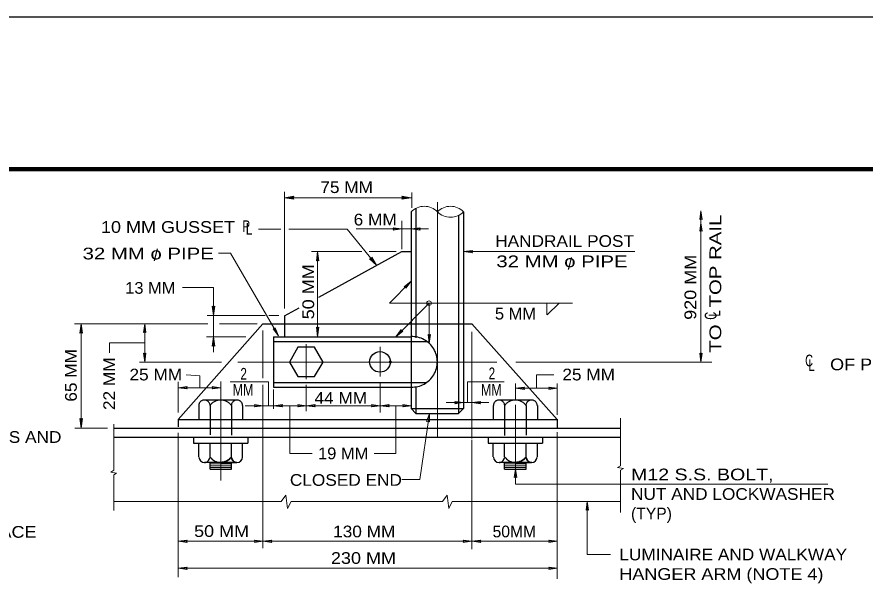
# Model space of a CAD drawing. Extents: x 312601.858 to 312602.699, y 144420.109 to 144420.704.
# Drawn here: x 312602.2633 to 312602.4805, y 144420.5557 to 144420.7035 of the extents above; entities that cross this region are included whole.
import ezdxf
from ezdxf.enums import TextEntityAlignment as Align

# ---------------------------------------------------------------- set-up
doc = ezdxf.new("R2010")
doc.units = 0
doc.header["$LTSCALE"] = 0.0012
doc.header["$PDMODE"] = 32
doc.header["$PDSIZE"] = 0.0006
for name, pattern in [('DOT_DASHED', [7.7, 5, -1.2, 0.3, -1.2]), ('LONG_DASHED', [7.5, 6, -1.5]), ('MEDIUM_DASHED', [4.5, 3, -1.5])]:
    doc.linetypes.add(name, pattern=pattern)
for name, color, linetype, lineweight in [('1', 7, 'Continuous', 13), ('2', 7, 'Continuous', 13), ('39', 7, 'Continuous', 13), ('4', 7, 'Continuous', 13)]:
    doc.layers.add(name, color=color, linetype=linetype, lineweight=lineweight)

msp = doc.modelspace()

# ---------------------------------------------------------------- hatches: boundary and pattern name
at = {"layer": '39'}
for points in [[(312602.334, 144420.6572), (312602.3342, 144420.6568), (312602.3318, 144420.6572), (312602.3342, 144420.6576)], [(312602.334, 144420.6572), (312602.3342, 144420.6568), (312602.3318, 144420.6572), (312602.3342, 144420.6576)], [(312602.3621, 144420.6572), (312602.3619, 144420.6576), (312602.3643, 144420.6572), (312602.3619, 144420.6568)], [(312602.3403, 144420.6412), (312602.34, 144420.641), (312602.3403, 144420.6434), (312602.3406, 144420.641)], [(312602.3403, 144420.6412), (312602.34, 144420.641), (312602.3403, 144420.6434), (312602.3406, 144420.641)], [(312602.354, 144420.6416), (312602.3542, 144420.642), (312602.3554, 144420.6399), (312602.3536, 144420.6415)], [(312602.3136, 144420.6292), (312602.314, 144420.6294), (312602.3136, 144420.627), (312602.3133, 144420.6294)], [(312602.2797, 144420.6227), (312602.2794, 144420.6225), (312602.2797, 144420.6249), (312602.2801, 144420.6225)], [(312602.3403, 144420.6238), (312602.3406, 144420.624), (312602.3403, 144420.6216), (312602.34, 144420.624)], [(312602.3136, 144420.6194), (312602.3133, 144420.6192), (312602.3136, 144420.6216), (312602.314, 144420.6192)], [(312602.3757, 144420.6047), (312602.3755, 144420.605), (312602.3777, 144420.6047), (312602.3755, 144420.6044)], [(312602.3818, 144420.6047), (312602.382, 144420.6044), (312602.3798, 144420.6047), (312602.382, 144420.605)], [(312602.2797, 144420.6004), (312602.2801, 144420.6006), (312602.2797, 144420.5982), (312602.2794, 144420.6006)]]:
    msp.add_hatch(color=256, dxfattribs=at).paths.add_polyline_path(points)

# ---------------------------------------------------------------- linework, layer by layer
at = {"layer": '1'}
for p, q in [((312602.3318, 144420.6587), (312602.3318, 144420.6288)), ((312602.3644, 144420.6546), (312602.3644, 144420.6585)), ((312602.3318, 144420.6572), (312602.3643, 144420.6572)), ((312602.3619, 144420.644), (312602.3619, 144420.6513)), ((312602.3252, 144420.6491), (312602.3309, 144420.6491)), ((312602.3329, 144420.6491), (312602.3479, 144420.6491)), ((312602.3479, 144420.6491), (312602.3554, 144420.6399)), ((312602.4385, 144420.6508), (312602.4385, 144420.6151)), ((312602.3149, 144420.643), (312602.318, 144420.643)), ((312602.318, 144420.643), (312602.3303, 144420.6218)), ((312602.3387, 144420.6434), (312602.3516, 144420.6434)), ((312602.3403, 144420.6434), (312602.3403, 144420.6216)), ((312602.3535, 144420.6434), (312602.3604, 144420.6434)), ((312602.3777, 144420.6434), (312602.4216, 144420.6434)), ((312602.3587, 144420.6302), (312602.3643, 144420.6358)), ((312602.3587, 144420.6302), (312602.4056, 144420.6302)), ((312602.3689, 144420.6302), (312602.3603, 144420.6216)), ((312602.3689, 144420.6301), (312602.3689, 144420.6199)), ((312602.399, 144420.6302), (312602.399, 144420.6272)), ((312602.3991, 144420.6272), (312602.4022, 144420.6302)), ((312602.3269, 144420.627), (312602.312, 144420.627)), ((312602.3304, 144420.627), (312602.3278, 144420.627)), ((312602.278, 144420.6249), (312602.3122, 144420.6249)), ((312602.2797, 144420.6249), (312602.2797, 144420.5982)), ((312602.296, 144420.6249), (312602.296, 144420.6152)), ((312602.3152, 144420.6249), (312602.3248, 144420.6249)), ((312602.3263, 144420.6232), (312602.3263, 144420.611)), ((312602.3118, 144420.6216), (312602.3219, 144420.6216)), ((312602.3136, 144420.6216), (312602.3136, 144420.6176)), ((312602.3798, 144420.6228), (312602.3798, 144420.5955)), ((312602.287, 144420.62), (312602.287, 144420.6175)), ((312602.2947, 144420.6151), (312602.3157, 144420.6151)), ((312602.3911, 144420.6151), (312602.4413, 144420.6151)), ((312602.3046, 144420.61), (312602.3046, 144420.6022)), ((312602.3179, 144420.61), (312602.3277, 144420.61)), ((312602.3787, 144420.61), (312602.3881, 144420.61)), ((312602.3046, 144420.6085), (312602.3155, 144420.6085)), ((312602.3263, 144420.6093), (312602.3263, 144420.5952)), ((312602.329, 144420.6081), (312602.329, 144420.6031)), ((312602.3563, 144420.6097), (312602.3563, 144420.6022)), ((312602.391, 144420.6096), (312602.391, 144420.6055)), ((312602.391, 144420.6084), (312602.4017, 144420.6084)), ((312602.4017, 144420.6096), (312602.4017, 144420.6016)), ((312602.3563, 144420.6039), (312602.3643, 144420.6039)), ((312602.2881, 144420.5992), (312602.2881, 144420.5874)), ((312602.4179, 144420.6007), (312602.4179, 144420.5885)), ((312602.2781, 144420.5982), (312602.2865, 144420.5982)), ((312602.3046, 144420.597), (312602.3046, 144420.56)), ((312602.4017, 144420.5971), (312602.4017, 144420.5596)), ((312602.3263, 144420.5952), (312602.3263, 144420.5674)), ((312602.3798, 144420.5952), (312602.3798, 144420.5672)), ((312602.3128, 144420.589), (312602.3182, 144420.589)), ((312602.3128, 144420.5885), (312602.3182, 144420.5885)), ((312602.3128, 144420.5881), (312602.3182, 144420.5881)), ((312602.3155, 144420.5894), (312602.3196, 144420.5894)), ((312602.3882, 144420.589), (312602.3937, 144420.589)), ((312602.3882, 144420.5885), (312602.3937, 144420.5885)), ((312602.3882, 144420.5881), (312602.3937, 144420.5881)), ((312602.4171, 144420.5881), (312602.4179, 144420.5885)), ((312602.4171, 144420.5881), (312602.4187, 144420.5878)), ((312602.2873, 144420.5869), (312602.2881, 144420.5874)), ((312602.2873, 144420.5869), (312602.2888, 144420.5866)), ((312602.2881, 144420.5862), (312602.2888, 144420.5866)), ((312602.2881, 144420.5862), (312602.2881, 144420.5771)), ((312602.391, 144420.5877), (312602.391, 144420.5838)), ((312602.4179, 144420.5874), (312602.4187, 144420.5878)), ((312602.4179, 144420.5874), (312602.4179, 144420.5766)), ((312602.391, 144420.5838), (312602.471, 144420.5838)), ((312602.2881, 144420.5794), (312602.331, 144420.5794)), ((312602.3335, 144420.5794), (312602.3723, 144420.5794)), ((312602.3748, 144420.5794), (312602.4179, 144420.5794)), ((312602.4094, 144420.5794), (312602.4094, 144420.5658)), ((312602.4094, 144420.5658), (312602.4153, 144420.5658)), ((312602.3046, 144420.5623), (312602.4017, 144420.5623))]:
    msp.add_line(p, q, dxfattribs=at)
at = {"layer": '1', "linetype": 'DOT_DASHED'}
for p, q in [((312602.371, 144420.6561), (312602.371, 144420.5959)), ((312602.3563, 144420.619), (312602.3563, 144420.6114)), ((312602.3199, 144420.6151), (312602.3862, 144420.6151)), ((312602.3155, 144420.6101), (312602.3155, 144420.5848)), ((312602.391, 144420.6041), (312602.391, 144420.5877))]:
    msp.add_line(p, q, dxfattribs=at)
at = {"layer": '1', "lineweight": 25}
for p, q in [((312602.3643, 144420.6536), (312602.3643, 144420.6249)), ((312602.3777, 144420.6536), (312602.3777, 144420.6249)), ((312602.3406, 144420.6317), (312602.3619, 144420.6434)), ((312602.3619, 144420.6434), (312602.3643, 144420.6434)), ((312602.3318, 144420.6269), (312602.3356, 144420.629)), ((312602.3318, 144420.6269), (312602.3318, 144420.6249)), ((312602.3046, 144420.6004), (312602.3263, 144420.6249)), ((312602.3263, 144420.6249), (312602.3798, 144420.6249)), ((312602.3798, 144420.6249), (312602.4017, 144420.6004)), ((312602.3046, 144420.6004), (312602.3046, 144420.5985)), ((312602.4017, 144420.6005), (312602.4017, 144420.5982)), ((312602.2881, 144420.5982), (312602.4179, 144420.5982)), ((312602.2881, 144420.5959), (312602.4179, 144420.5959)), ((312602.3224, 144420.5959), (312602.3224, 144420.5943)), ((312602.3979, 144420.5959), (312602.3979, 144420.5943)), ((312602.3099, 144420.5908), (312602.3099, 144420.5943)), ((312602.3128, 144420.5908), (312602.3128, 144420.5943)), ((312602.3182, 144420.5908), (312602.3182, 144420.5943)), ((312602.3211, 144420.5908), (312602.3211, 144420.5943)), ((312602.3853, 144420.5908), (312602.3853, 144420.5943)), ((312602.3882, 144420.5908), (312602.3882, 144420.5943)), ((312602.3937, 144420.5908), (312602.3937, 144420.5943)), ((312602.3966, 144420.5908), (312602.3966, 144420.5943)), ((312602.3128, 144420.5877), (312602.3128, 144420.5894)), ((312602.3182, 144420.5877), (312602.3182, 144420.5894)), ((312602.3882, 144420.5877), (312602.3882, 144420.5894)), ((312602.391, 144420.5894), (312602.3951, 144420.5894)), ((312602.3937, 144420.5877), (312602.3937, 144420.5894)), ((312602.3128, 144420.5877), (312602.3182, 144420.5877)), ((312602.3882, 144420.5877), (312602.3937, 144420.5877))]:
    msp.add_line(p, q, dxfattribs=at)
at = {"layer": '1', "linetype": 'LONG_DASHED', "lineweight": 25}
for p, q in [((312602.3655, 144420.6545), (312602.3655, 144420.6213)), ((312602.3764, 144420.6527), (312602.3764, 144420.6249)), ((312602.3318, 144420.6249), (312602.3318, 144420.6216)), ((312602.3643, 144420.6249), (312602.3643, 144420.6032)), ((312602.3764, 144420.6249), (312602.3764, 144420.6019)), ((312602.3777, 144420.6249), (312602.3777, 144420.6032)), ((312602.329, 144420.6216), (312602.329, 144420.6087)), ((312602.329, 144420.6216), (312602.3642, 144420.6216)), ((312602.329, 144420.6204), (312602.3683, 144420.6204)), ((312602.329, 144420.6099), (312602.3682, 144420.6099)), ((312602.329, 144420.6087), (312602.3643, 144420.6087)), ((312602.3655, 144420.6088), (312602.3655, 144420.6019)), ((312602.3128, 144420.604), (312602.3128, 144420.5965)), ((312602.3182, 144420.604), (312602.3182, 144420.5964)), ((312602.3882, 144420.604), (312602.3882, 144420.5963)), ((312602.3937, 144420.604), (312602.3937, 144420.5964)), ((312602.3643, 144420.6032), (312602.3655, 144420.6019)), ((312602.3643, 144420.6032), (312602.3777, 144420.6032)), ((312602.3655, 144420.6019), (312602.3764, 144420.6019)), ((312602.3764, 144420.6019), (312602.3777, 144420.6032)), ((312602.3046, 144420.6004), (312602.4016, 144420.6004))]:
    msp.add_line(p, q, dxfattribs=at)
at = {"layer": '1', "linetype": 'MEDIUM_DASHED', "lineweight": 25}
for p, q in [((312602.3099, 144420.604), (312602.3099, 144420.6004)), ((312602.3113, 144420.6054), (312602.3196, 144420.6054)), ((312602.3211, 144420.604), (312602.3211, 144420.6004)), ((312602.3853, 144420.604), (312602.3853, 144420.6004)), ((312602.3868, 144420.6054), (312602.3951, 144420.6054)), ((312602.3966, 144420.604), (312602.3966, 144420.6004))]:
    msp.add_line(p, q, dxfattribs=at)
at = {"layer": '1'}
for points in [[(312602.4382, 144420.6516), (312602.4385, 144420.6538), (312602.4388, 144420.6516), (312602.4385, 144420.6518)], [(312602.3597, 144420.6495), (312602.3619, 144420.6492), (312602.3597, 144420.6489), (312602.3599, 144420.6492)], [(312602.3666, 144420.6489), (312602.3643, 144420.6492), (312602.3666, 144420.6495), (312602.3663, 144420.6492)], [(312602.4382, 144420.6486), (312602.4385, 144420.6508), (312602.4388, 144420.6486), (312602.4385, 144420.6488)], [(312602.38, 144420.6431), (312602.3777, 144420.6434), (312602.38, 144420.6437), (312602.3797, 144420.6434)], [(312602.3625, 144420.6344), (312602.3643, 144420.6358), (312602.3629, 144420.634), (312602.3629, 144420.6344)], [(312602.2957, 144420.6227), (312602.296, 144420.6249), (312602.2963, 144420.6227), (312602.296, 144420.6229)], [(312602.3294, 144420.6239), (312602.3303, 144420.6218), (312602.3289, 144420.6236), (312602.3293, 144420.6236)], [(312602.3621, 144420.623), (312602.3603, 144420.6216), (312602.3617, 144420.6234), (312602.3617, 144420.623)], [(312602.3692, 144420.6222), (312602.3689, 144420.6199), (312602.3686, 144420.6222), (312602.3689, 144420.6219)], [(312602.2963, 144420.6174), (312602.296, 144420.6151), (312602.2957, 144420.6174), (312602.296, 144420.6171)], [(312602.4388, 144420.6174), (312602.4385, 144420.6151), (312602.4382, 144420.6174), (312602.4385, 144420.6171)], [(312602.3069, 144420.6082), (312602.3046, 144420.6085), (312602.3069, 144420.6088), (312602.3066, 144420.6085)], [(312602.3133, 144420.6088), (312602.3155, 144420.6085), (312602.3133, 144420.6082), (312602.3135, 144420.6085)], [(312602.3933, 144420.6081), (312602.391, 144420.6084), (312602.3933, 144420.6087), (312602.393, 144420.6084)], [(312602.3995, 144420.6087), (312602.4017, 144420.6084), (312602.3995, 144420.6081), (312602.3997, 144420.6084)], [(312602.3241, 144420.6042), (312602.3263, 144420.6039), (312602.3241, 144420.6036), (312602.3243, 144420.6039)], [(312602.3313, 144420.6036), (312602.329, 144420.6039), (312602.3313, 144420.6042), (312602.331, 144420.6039)], [(312602.3352, 144420.6042), (312602.3374, 144420.6039), (312602.3352, 144420.6036), (312602.3354, 144420.6039)], [(312602.3397, 144420.6036), (312602.3374, 144420.6039), (312602.3397, 144420.6042), (312602.3394, 144420.6039)], [(312602.3541, 144420.6042), (312602.3563, 144420.6039), (312602.3541, 144420.6036), (312602.3543, 144420.6039)], [(312602.3586, 144420.6036), (312602.3563, 144420.6039), (312602.3586, 144420.6042), (312602.3583, 144420.6039)], [(312602.3621, 144420.6042), (312602.3643, 144420.6039), (312602.3621, 144420.6036), (312602.3623, 144420.6039)], [(312602.3682, 144420.5999), (312602.369, 144420.6019), (312602.369, 144420.5998), (312602.3687, 144420.6)], [(312602.3907, 144420.5855), (312602.391, 144420.5877), (312602.3913, 144420.5855), (312602.391, 144420.5857)], [(312602.4091, 144420.5772), (312602.4094, 144420.5794), (312602.4097, 144420.5772), (312602.4094, 144420.5774)], [(312602.3069, 144420.5689), (312602.3046, 144420.5692), (312602.3069, 144420.5695), (312602.3066, 144420.5692)], [(312602.3241, 144420.5695), (312602.3263, 144420.5692), (312602.3241, 144420.5689), (312602.3243, 144420.5692)], [(312602.3286, 144420.5689), (312602.3263, 144420.5692), (312602.3286, 144420.5695), (312602.3283, 144420.5692)], [(312602.3776, 144420.5695), (312602.3798, 144420.5692), (312602.3776, 144420.5689), (312602.3778, 144420.5692)], [(312602.3821, 144420.5689), (312602.3798, 144420.5692), (312602.3821, 144420.5695), (312602.3818, 144420.5692)], [(312602.3995, 144420.5695), (312602.4017, 144420.5692), (312602.3995, 144420.5689), (312602.3997, 144420.5692)], [(312602.3069, 144420.562), (312602.3046, 144420.5623), (312602.3069, 144420.5626), (312602.3066, 144420.5623)], [(312602.3995, 144420.5626), (312602.4017, 144420.5623), (312602.3995, 144420.562), (312602.3997, 144420.5623)]]:
    msp.add_lwpolyline(points, close=True, dxfattribs=at)
for points in [[(312602.3502, 144420.6492), (312602.3619, 144420.6492), (312602.3643, 144420.6492), (312602.3687, 144420.6492)], [(312602.3136, 144420.6342), (312602.3136, 144420.627), (312602.3136, 144420.6216)], [(312602.3589, 144420.6151), (312602.3593, 144420.6151), (312602.3592, 144420.6151)], [(312602.3217, 144420.6039), (312602.3263, 144420.6039), (312602.329, 144420.6039)], [(312602.329, 144420.6039), (312602.3374, 144420.6039), (312602.3563, 144420.6039), (312602.3563, 144420.6039)], [(312602.3732, 144420.6047), (312602.3777, 144420.6047), (312602.3798, 144420.6047), (312602.3842, 144420.6047)], [(312602.369, 144420.6019), (312602.3665, 144420.585), (312602.3619, 144420.585)], [(312602.331, 144420.5794), (312602.3322, 144420.581), (312602.3326, 144420.5776), (312602.3335, 144420.5794)], [(312602.3723, 144420.5794), (312602.3735, 144420.581), (312602.3739, 144420.5776), (312602.3748, 144420.5794)], [(312602.3046, 144420.5692), (312602.3263, 144420.5692), (312602.3798, 144420.5692), (312602.4017, 144420.5692)]]:
    msp.add_lwpolyline(points, dxfattribs=at)
at = {"layer": '1', "lineweight": 25}
msp.add_lwpolyline([(312602.3352, 144420.6114), (312602.3395, 144420.6114), (312602.3417, 144420.6151), (312602.3395, 144420.6189), (312602.3352, 144420.6189), (312602.3331, 144420.6151)], close=True, dxfattribs=at)
for points in [[(312602.3085, 144420.5959), (312602.3085, 144420.5943), (312602.3224, 144420.5943)], [(312602.384, 144420.5959), (312602.384, 144420.5943), (312602.3979, 144420.5943)], [(312602.3155, 144420.5894), (312602.3113, 144420.5894), (312602.3116, 144420.5894)], [(312602.391, 144420.5894), (312602.3868, 144420.5894), (312602.387, 144420.5894)]]:
    msp.add_lwpolyline(points, dxfattribs=at)
at = {"layer": '1', "lineweight": 35}
for points in [[(312602.3155, 144420.5894), (312602.3196, 144420.5894), (312602.3194, 144420.5894)], [(312602.391, 144420.5894), (312602.3951, 144420.5894), (312602.3949, 144420.5894)]]:
    msp.add_lwpolyline(points, dxfattribs=at)
at = {"layer": '1'}
msp.add_circle((312602.36885, 144420.63019), 0.000595, dxfattribs=at)
at = {"layer": '1', "lineweight": 25}
msp.add_circle((312602.35627, 144420.615145), 0.002635, dxfattribs=at)
at = {"layer": '1', "linetype": 'LONG_DASHED', "lineweight": 25}
msp.add_arc((312602.36451, 144420.615145), 0.006465, 267.78238, 92.21762, dxfattribs=at)
at = {"layer": '1', "linetype": 'MEDIUM_DASHED', "lineweight": 25}
for centre, radius, start, end in [((312602.311305, 144420.603922), 0.001448, 3.47141, 176.52859), ((312602.31547, 144420.60197), 0.0034, 36.8699, 143.1301), ((312602.319635, 144420.603922), 0.001448, 3.47141, 176.52859), ((312602.386785, 144420.603922), 0.001448, 3.47141, 176.52859), ((312602.39095, 144420.60197), 0.0034, 36.8699, 143.1301), ((312602.395115, 144420.603922), 0.001448, 3.47141, 176.52859)]:
    msp.add_arc(centre, radius, start, end, dxfattribs=at)
at = {"layer": '1', "lineweight": 25}
for centre, radius, start, end in [((312602.311305, 144420.590838), 0.001448, 280.13588, 356.52859), ((312602.31547, 144420.59279), 0.0034, 216.8699, 270), ((312602.319635, 144420.590838), 0.001448, 183.47141, 356.52859), ((312602.386785, 144420.590838), 0.001448, 183.47141, 270), ((312602.386785, 144420.590838), 0.001448, 280.13588, 356.52859), ((312602.39095, 144420.59279), 0.0034, 216.8699, 270), ((312602.395115, 144420.590838), 0.001448, 183.47141, 356.52859)]:
    msp.add_arc(centre, radius, start, end, dxfattribs=at)
at = {"layer": '1'}
for centre in [(312602.31547, 144420.59279), (312602.39095, 144420.59279)]:
    msp.add_arc(centre, 0.0034, 269.99962, 323.1301, dxfattribs=at)
at = {"layer": '1', "lineweight": 35}
for centre, radius, start, end in [((312602.31547, 144420.59279), 0.0034, 270, 323.1301), ((312602.319635, 144420.590838), 0.001448, 183.47141, 259.86412), ((312602.39095, 144420.59279), 0.0034, 270, 323.1301), ((312602.395115, 144420.590838), 0.001448, 183.47141, 259.86412)]:
    msp.add_arc(centre, radius, start, end, dxfattribs=at)
at = {"layer": '1', "lineweight": 25}
msp.add_ellipse((312602.311305, 144420.590838), major_axis=(0.000088, -0.001445), ratio=0.974511, start_param=4.712389, end_param=6.2225978, dxfattribs=at)
at = {"layer": '1'}
msp.add_point((312602.3589, 144420.6151), dxfattribs=at)
at = {"layer": '2'}
for p, q in [((312602.4385, 144420.6508), (312602.4385, 144420.6538)), ((312602.3136, 144420.6342), (312602.3057, 144420.6342)), ((312602.296, 144420.62), (312602.287, 144420.62)), ((312602.3277, 144420.6039), (312602.3277, 144420.61)), ((312602.3787, 144420.6047), (312602.3787, 144420.61)), ((312602.4008, 144420.6118), (312602.3964, 144420.6118)), ((312602.3964, 144420.6084), (312602.3964, 144420.6118)), ((312602.3374, 144420.6093), (312602.3374, 144420.6025)), ((312602.3332, 144420.6039), (312602.3332, 144420.5917)), ((312602.3603, 144420.6039), (312602.3603, 144420.5917)), ((312602.3332, 144420.5917), (312602.3389, 144420.5917)), ((312602.3548, 144420.5917), (312602.3603, 144420.5917))]:
    msp.add_line(p, q, dxfattribs=at)
at = {"layer": '2', "linetype": 'DOT_DASHED'}
msp.add_line((312602.3374, 144420.6197), (312602.3374, 144420.6107), dxfattribs=at)
at = {"layer": '2'}
msp.add_lwpolyline([(312602.3101, 144420.6085), (312602.3101, 144420.6116), (312602.3066, 144420.6118)], dxfattribs=at)
at = {"layer": '39', "lineweight": 25}
msp.add_line((312601.8578, 144420.7035), (312602.6988, 144420.7035), dxfattribs=at)
at = {"layer": '39', "lineweight": 158}
msp.add_lwpolyline([(312601.9088, 144420.1247), (312601.9088, 144420.6645), (312602.6838, 144420.6645)], dxfattribs=at)
at = {"layer": '39'}
for points in [[(312602.334, 144420.6572), (312602.3342, 144420.6568), (312602.3318, 144420.6572), (312602.3342, 144420.6576)], [(312602.334, 144420.6572), (312602.3342, 144420.6568), (312602.3318, 144420.6572), (312602.3342, 144420.6576)], [(312602.3621, 144420.6572), (312602.3619, 144420.6576), (312602.3643, 144420.6572), (312602.3619, 144420.6568)], [(312602.3403, 144420.6412), (312602.34, 144420.641), (312602.3403, 144420.6434), (312602.3406, 144420.641)], [(312602.3403, 144420.6412), (312602.34, 144420.641), (312602.3403, 144420.6434), (312602.3406, 144420.641)], [(312602.354, 144420.6416), (312602.3542, 144420.642), (312602.3554, 144420.6399), (312602.3536, 144420.6415)], [(312602.3136, 144420.6292), (312602.314, 144420.6294), (312602.3136, 144420.627), (312602.3133, 144420.6294)], [(312602.2797, 144420.6227), (312602.2794, 144420.6225), (312602.2797, 144420.6249), (312602.2801, 144420.6225)], [(312602.3403, 144420.6238), (312602.3406, 144420.624), (312602.3403, 144420.6216), (312602.34, 144420.624)], [(312602.3136, 144420.6194), (312602.3133, 144420.6192), (312602.3136, 144420.6216), (312602.314, 144420.6192)], [(312602.3757, 144420.6047), (312602.3755, 144420.605), (312602.3777, 144420.6047), (312602.3755, 144420.6044)], [(312602.3818, 144420.6047), (312602.382, 144420.6044), (312602.3798, 144420.6047), (312602.382, 144420.605)], [(312602.2797, 144420.6004), (312602.2801, 144420.6006), (312602.2797, 144420.5982), (312602.2794, 144420.6006)]]:
    msp.add_lwpolyline(points, close=True, dxfattribs=at)
at = {"layer": '4'}
for centre, start, end in [((312602.36765, 144420.650293), 44.63115, 135.36885), ((312602.37435, 144420.650293), 44.63115, 135.36885), ((312602.37435, 144420.656907), 224.63115, 315.36885)]:
    msp.add_arc(centre, 0.004707, start, end, dxfattribs=at)

# ---------------------------------------------------------------- texts
at = {"layer": '2'}
for s, width, p in [('75 MM', 1.1, (312602.34775, 144420.6584)), ('6 MM', 1.1, (312602.35505, 144420.6501)), ('32 MM o PIPE', 1.3, (312602.2969, 144420.6414)), ('32 MM o PIPE', 1.3, (312602.4029, 144420.6394)), ('13 MM', 1.05, (312602.29745, 144420.6326)), ('5 MM', 1.05, (312602.391, 144420.626)), ('25 MM', 1.1, (312602.29885, 144420.6104)), ('2', 0.75, (312602.32135, 144420.6106)), ('2', 0.75, (312602.38495, 144420.6107)), ('25 MM', 1.1, (312602.40975, 144420.6104)), ('MM', 0.8, (312602.3212, 144420.6065)), ('MM', 0.8, (312602.3848, 144420.6065)), ('44 MM', 1.1, (312602.34625, 144420.6044)), ('19 MM', 1.05, (312602.34685, 144420.5902)), ('SIGN PANEL FACE', 1.15, (312602.24765, 144420.5701)), ('50 MM', 1.15, (312602.3157, 144420.5703)), ('130 MM', 1.1, (312602.35225, 144420.5702)), ('230 MM', 1.15, (312602.35205, 144420.5634))]:
    msp.add_text(s, height=0.003, dxfattribs=dict(at, width=width)).set_placement(p, align=Align.CENTER)
for s, width, p in [('10 MM GUSSET', 1.15, (312602.2848, 144420.6482)), ('P', 0.75, (312602.321, 144420.6484)), ('L', 0.75, (312602.3219, 144420.6477)), ('HANDRAIL POST', 1.1, (312602.3858, 144420.6446)), ('C', 0.7, (312602.4652, 144420.614)), ('L', 0.75, (312602.466, 144420.6128)), ('OF PIPE', 1.15, (312602.4716, 144420.613)), ('WITH LOCKNUTS AND', 1.1, (312602.2276, 144420.5944)), ('CLOSED END', 1.1, (312602.3332, 144420.5834)), ('M12 S.S. BOLT,', 1.25, (312602.4206, 144420.5848)), ('NUT AND LOCKWASHER ', 1.1, (312602.4206, 144420.5798)), ('LUMINAIRE AND WALKWAY', 1.1, (312602.4176, 144420.5643)), ('HANGER ARM (NOTE 4) ', 1.15, (312602.4176, 144420.5593))]:
    msp.add_text(s, height=0.003, dxfattribs=dict(at, width=width)).set_placement(p)
at = {"layer": '2', "width": 1.3}
msp.add_text('TO   TOP RAIL', height=0.003, rotation=90, dxfattribs=at).set_placement((312602.4437, 144420.6175))
at = {"layer": '2'}
for s, p in [('/', (312602.29885, 144420.641)), ('/', (312602.40495, 144420.6388)), ('50MM', (312602.3907, 144420.5702))]:
    msp.add_text(s, height=0.003, dxfattribs=at).set_placement(p, align=Align.CENTER)
for s, height, width, p in [('920 MM', 0.003, 1.15, (312602.4373, 144420.63425)), ('50 MM', 0.003, 1.15, (312602.3394, 144420.6331)), ('C', 0.002999, 0.7, (312602.4425, 144420.62695)), ('L', 0.002999, 0.75, (312602.4435, 144420.62755)), ('65 MM', 0.003, 1.1, (312602.2786, 144420.6117)), ('22 MM', 0.003, 1.1, (312602.2884, 144420.60955))]:
    msp.add_text(s, height=height, rotation=90, dxfattribs=dict(at, width=width)).set_placement(p, align=Align.CENTER)
msp.add_text('(TYP)', height=0.003, dxfattribs=at).set_placement((312602.4206, 144420.5748))

doc.saveas('drawing.dxf')
